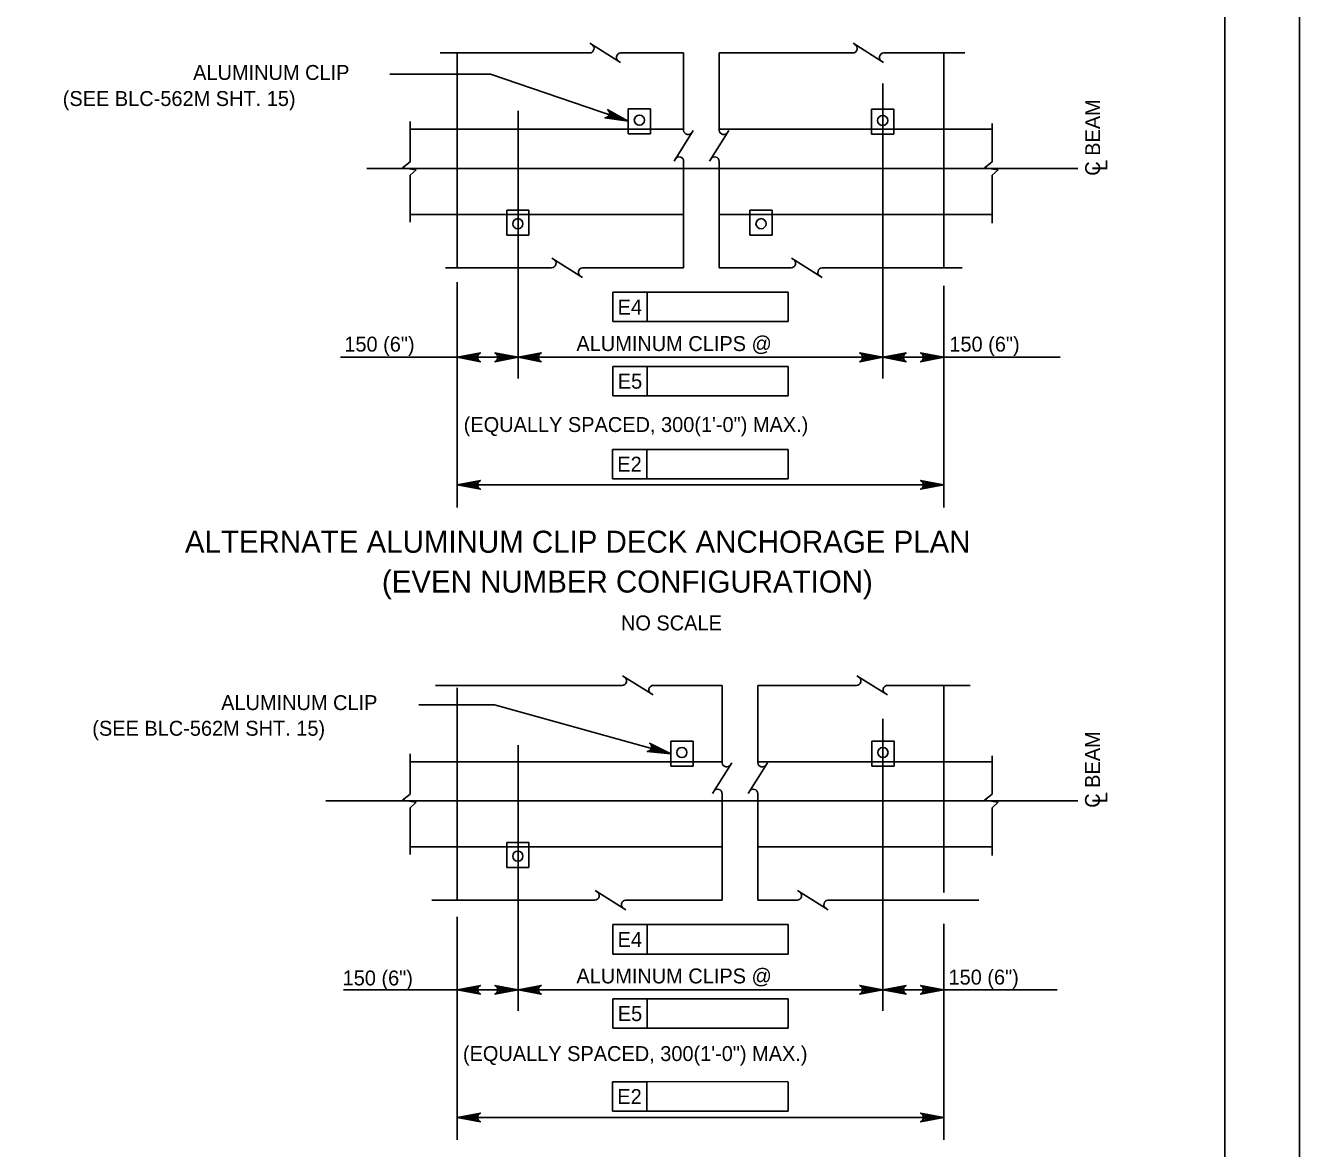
# Model space of a CAD drawing. Extents: x 638263 to 640360, y 293683 to 298655.
# Drawn here: x 639861.3 to 640117.5, y 295708.4 to 295934.1 of the extents above; entities that cross this region are included whole.
import ezdxf

# ---------------------------------------------------------------- set-up
doc = ezdxf.new("R2010")
doc.units = 0
for name, color, linetype in [('2', 7, 'Continuous'), ('3', 7, 'Continuous'), ('4', 7, 'Continuous'), ('8', 7, 'Continuous'), ('9', 7, 'Continuous'), ('PLT-BNDY', 7, 'Continuous')]:
    doc.layers.add(name, color=color, linetype=linetype)

msp = doc.modelspace()

# ---------------------------------------------------------------- linework, layer by layer
at = {"layer": '2'}
for p, q in [((640102.46, 296044.46), (640102.46, 295480.46)), ((639948.08, 295885.4), (639948.08, 295928.58)), ((640045.92, 295885.4), (640045.92, 295928.58)), ((639948.08, 295758.28), (639948.08, 295800.94)), ((640045.92, 295759.8), (640045.92, 295801.5))]:
    msp.add_line(p, q, dxfattribs=at)
at = {"layer": '3'}
for p, q in [((639974.77, 295930.52), (639980.92, 295926.65)), ((640027.67, 295930.52), (640033.82, 295926.65)), ((639944.64, 295928.58), (639974.69, 295928.58)), ((639980.91, 295928.58), (639993.61, 295928.58)), ((639993.61, 295913.01), (639993.61, 295928.58)), ((640000.76, 295913.01), (640000.76, 295928.58)), ((640000.76, 295928.58), (640027.59, 295928.58)), ((640033.81, 295928.58), (640050.15, 295928.58)), ((639938.58, 295906.7), (639938.58, 295914.8)), ((640055.66, 295906.7), (640055.66, 295914.42)), ((639938.58, 295913.23), (639993.61, 295913.23)), ((639991.67, 295906.86), (639995.54, 295913.02)), ((639998.83, 295906.86), (640002.7, 295913.02)), ((640000.76, 295913.23), (640055.66, 295913.23)), ((639937.04, 295905.51), (639938.58, 295906.7)), ((639993.61, 295885.4), (639993.61, 295906.79)), ((640000.76, 295885.4), (640000.76, 295906.79)), ((640054.12, 295905.51), (640055.66, 295906.7)), ((639939.8, 295905.08), (639937.04, 295905.51)), ((639938.58, 295903.99), (639939.8, 295905.08)), ((639938.58, 295894.57), (639938.58, 295903.99)), ((640056.88, 295905.08), (640054.12, 295905.51)), ((640055.66, 295903.99), (640056.88, 295905.08)), ((640055.66, 295894.38), (640055.66, 295903.99)), ((639993.61, 295896.11), (639938.58, 295896.11)), ((640055.66, 295896.11), (640000.76, 295896.11)), ((639945.69, 295885.4), (639967.04, 295885.4)), ((639967.11, 295887.33), (639973.27, 295883.46)), ((639973.26, 295885.4), (639993.61, 295885.4)), ((640000.76, 295885.4), (640015.22, 295885.4)), ((640015.29, 295887.33), (640021.45, 295883.46)), ((640021.44, 295885.4), (640049.62, 295885.4)), ((639981.29, 295803.4), (639987.45, 295799.53)), ((640028.41, 295803.4), (640034.57, 295799.53)), ((639943.68, 295801.46), (639981.22, 295801.46)), ((639987.44, 295801.46), (640001.37, 295801.46)), ((640001.37, 295785.88), (640001.37, 295801.46)), ((640008.53, 295801.46), (640028.34, 295801.46)), ((640008.53, 295785.88), (640008.53, 295801.46)), ((640034.56, 295801.46), (640051.22, 295801.46)), ((639938.58, 295779.58), (639938.58, 295787.68)), ((639938.58, 295786.11), (640001.37, 295786.11)), ((639999.43, 295779.74), (640003.3, 295785.9)), ((640006.59, 295779.74), (640010.46, 295785.9)), ((640008.53, 295786.11), (640055.66, 295786.11)), ((640055.66, 295779.58), (640055.66, 295787.3)), ((639937.04, 295778.39), (639938.58, 295779.58)), ((639939.8, 295777.96), (639937.04, 295778.39)), ((639938.58, 295776.87), (639939.8, 295777.96)), ((640001.37, 295758.28), (640001.37, 295779.67)), ((640008.53, 295758.28), (640008.53, 295779.67)), ((640054.12, 295778.39), (640055.66, 295779.58)), ((640056.88, 295777.96), (640054.12, 295778.39)), ((640055.66, 295776.87), (640056.88, 295777.96)), ((639938.58, 295767.45), (639938.58, 295776.87)), ((640055.66, 295767.26), (640055.66, 295776.87)), ((640001.37, 295768.99), (639938.58, 295768.99)), ((640055.66, 295768.99), (640008.53, 295768.99)), ((639975.79, 295760.21), (639981.95, 295756.34)), ((640016.49, 295760.21), (640022.65, 295756.34)), ((639942.99, 295758.28), (639975.72, 295758.28)), ((639981.94, 295758.28), (640001.37, 295758.28)), ((640008.53, 295758.28), (640016.42, 295758.28)), ((640022.64, 295758.28), (640052.96, 295758.28))]:
    msp.add_line(p, q, dxfattribs=at)
for centre in [(639984.71, 295915.07), (640033.63, 295915.01), (639960.25, 295894.26), (640009.17, 295894.26), (639993.26, 295787.95), (640033.69, 295787.95), (639960.25, 295767.14)]:
    msp.add_circle(centre, 1.02, dxfattribs=at)
for centre, start, end in [((639974.69, 295929.49), 270, 60), ((640027.59, 295929.49), 270, 60), ((639980.99, 295927.68), 95.3286, 237.8672), ((640033.89, 295927.68), 95.3286, 237.8672), ((639994.51, 295913.09), 185.3286, 327.8672), ((640001.67, 295913.09), 185.3286, 327.8672), ((639992.7, 295906.79), 0, 150), ((639999.85, 295906.79), 0, 150), ((639967.04, 295886.31), 270, 60), ((639973.34, 295884.49), 95.3286, 237.8672), ((640015.22, 295886.31), 270, 60), ((640021.52, 295884.49), 95.3286, 237.8672), ((639981.22, 295802.37), 270, 60), ((639987.52, 295800.56), 95.3286, 237.8672), ((640028.34, 295802.37), 270, 60), ((640034.64, 295800.56), 95.3286, 237.8672), ((640002.27, 295785.97), 185.3286, 327.8672), ((640009.43, 295785.97), 185.3286, 327.8672), ((640000.46, 295779.67), 0, 150), ((640007.62, 295779.67), 0, 150), ((639975.72, 295759.19), 270, 60), ((640016.42, 295759.19), 270, 60), ((639982.02, 295757.37), 95.3286, 237.8672), ((640022.72, 295757.37), 95.3286, 237.8672)]:
    msp.add_arc(centre, 0.909, start, end, dxfattribs=at)
at = {"layer": '4'}
for p, q in [((639954.77, 295924.32), (639934.55, 295924.32)), ((640072.85, 295905.34), (639929.93, 295905.34)), ((639979.35, 295880.48), (639979.35, 295874.57)), ((639986.24, 295880.48), (639979.35, 295880.48)), ((639986.24, 295874.57), (639986.24, 295880.48)), ((640014.65, 295880.48), (639986.24, 295880.48)), ((640014.65, 295880.48), (640014.65, 295874.57)), ((639948.08, 295876.08), (639948.08, 295837.24)), ((640045.92, 295876.08), (640045.92, 295837.24)), ((639979.35, 295874.57), (640014.65, 295874.57)), ((639948.08, 295867.4), (639960.31, 295867.4)), ((640033.69, 295867.4), (640045.92, 295867.4)), ((639979.35, 295865.57), (639979.35, 295859.67)), ((639986.24, 295865.57), (639979.35, 295865.57)), ((640014.65, 295865.57), (639986.24, 295865.57)), ((639986.24, 295859.67), (639986.24, 295865.57)), ((640014.65, 295865.57), (640014.65, 295859.67)), ((639979.35, 295859.67), (640014.65, 295859.67)), ((639979.31, 295848.89), (639986.2, 295848.89)), ((639979.31, 295842.99), (639979.31, 295848.89)), ((639986.2, 295842.99), (639986.2, 295848.89)), ((639986.2, 295848.89), (640014.61, 295848.89)), ((640014.61, 295848.89), (640014.61, 295842.99)), ((640045.92, 295841.74), (639948.08, 295841.74)), ((640014.61, 295842.99), (639979.31, 295842.99)), ((639955.6, 295797.56), (639940.34, 295797.56)), ((640072.85, 295778.22), (639921.63, 295778.22)), ((639979.35, 295753.36), (639979.35, 295747.45)), ((639986.24, 295753.36), (639979.35, 295753.36)), ((639986.24, 295747.45), (639986.24, 295753.36)), ((640014.65, 295753.36), (639986.24, 295753.36)), ((640014.65, 295753.36), (640014.65, 295747.45)), ((639948.08, 295748.96), (639948.08, 295710.12)), ((639979.35, 295747.45), (640014.65, 295747.45)), ((640045.92, 295748.96), (640045.92, 295710.12)), ((639948.08, 295740.27), (639960.31, 295740.27)), ((640033.69, 295740.27), (640045.92, 295740.27)), ((639979.35, 295738.45), (639979.35, 295732.55)), ((639986.24, 295738.45), (639979.35, 295738.45)), ((640014.65, 295738.45), (639986.24, 295738.45)), ((639986.24, 295732.55), (639986.24, 295738.45)), ((640014.65, 295738.45), (640014.65, 295732.55)), ((639979.35, 295732.55), (640014.65, 295732.55)), ((639979.31, 295721.77), (639986.13, 295721.78)), ((639979.31, 295715.87), (639979.31, 295721.77)), ((639986.13, 295721.78), (640014.56, 295721.8)), ((639986.2, 295715.87), (639986.2, 295721.77)), ((640014.61, 295721.77), (640014.61, 295715.87)), ((640045.92, 295714.62), (639948.08, 295714.62)), ((640014.61, 295715.87), (639979.31, 295715.87))]:
    msp.add_line(p, q, dxfattribs=at)
for points in [[(639982.48, 295914.85), (639954.77, 295924.32)], [(639982.48, 295914.85), (639977.78, 295915.53), (639978.2, 295915.65), (639978.48, 295915.88), (639978.63, 295916.16), (639978.68, 295916.47), (639978.61, 295916.83), (639978.35, 295917.18), (639982.48, 295914.85), (639978.61, 295916.83), (639978.68, 295916.47), (639982.48, 295914.85), (639978.63, 295916.16), (639978.48, 295915.88), (639982.48, 295914.85), (639978.2, 295915.65)], [(639948.08, 295867.4), (639952.74, 295868.27), (639952.38, 295868.02), (639952.2, 295867.71), (639952.14, 295867.4), (639952.2, 295867.08), (639952.38, 295866.77), (639952.74, 295866.52), (639948.08, 295867.4), (639952.38, 295866.77), (639952.2, 295867.08), (639948.08, 295867.4), (639952.14, 295867.4), (639952.2, 295867.71), (639948.08, 295867.4), (639952.38, 295868.02)], [(639960.31, 295867.4), (639955.65, 295866.52), (639956.01, 295866.77), (639956.19, 295867.08), (639956.25, 295867.4), (639956.19, 295867.71), (639956.01, 295868.02), (639955.65, 295868.27), (639960.31, 295867.4), (639956.01, 295868.02), (639956.19, 295867.71), (639960.31, 295867.4), (639956.25, 295867.4), (639956.19, 295867.08), (639960.31, 295867.4), (639956.01, 295866.77)], [(639960.31, 295867.4), (639964.97, 295868.27), (639964.61, 295868.02), (639964.43, 295867.71), (639964.37, 295867.4), (639964.43, 295867.08), (639964.61, 295866.77), (639964.97, 295866.52), (639960.31, 295867.4), (639964.61, 295866.77), (639964.43, 295867.08), (639960.31, 295867.4), (639964.37, 295867.4), (639964.43, 295867.71), (639960.31, 295867.4), (639964.61, 295868.02)], [(640033.69, 295867.4), (640029.03, 295866.52), (640029.39, 295866.77), (640029.57, 295867.08), (640029.63, 295867.4), (640029.57, 295867.71), (640029.39, 295868.02), (640029.03, 295868.27), (640033.69, 295867.4), (640029.39, 295868.02), (640029.57, 295867.71), (640033.69, 295867.4), (640029.63, 295867.4), (640029.57, 295867.08), (640033.69, 295867.4), (640029.39, 295866.77)], [(640033.69, 295867.4), (640038.35, 295868.27), (640037.99, 295868.02), (640037.81, 295867.71), (640037.75, 295867.4), (640037.81, 295867.08), (640037.99, 295866.77), (640038.35, 295866.52), (640033.69, 295867.4), (640037.99, 295866.77), (640037.81, 295867.08), (640033.69, 295867.4), (640037.75, 295867.4), (640037.81, 295867.71), (640033.69, 295867.4), (640037.99, 295868.02)], [(640045.92, 295867.4), (640041.26, 295866.52), (640041.62, 295866.77), (640041.8, 295867.08), (640041.86, 295867.4), (640041.8, 295867.71), (640041.62, 295868.02), (640041.26, 295868.27), (640045.92, 295867.4), (640041.62, 295868.02), (640041.8, 295867.71), (640045.92, 295867.4), (640041.86, 295867.4), (640041.8, 295867.08), (640045.92, 295867.4), (640041.62, 295866.77)], [(639948.08, 295841.74), (639952.74, 295842.61), (639952.38, 295842.36), (639952.2, 295842.05), (639952.14, 295841.74), (639952.2, 295841.43), (639952.38, 295841.11), (639952.74, 295840.87), (639948.08, 295841.74), (639952.38, 295841.11), (639952.2, 295841.43), (639948.08, 295841.74), (639952.14, 295841.74), (639952.2, 295842.05), (639948.08, 295841.74), (639952.38, 295842.36)], [(640045.92, 295841.74), (640041.26, 295840.87), (640041.62, 295841.11), (640041.8, 295841.43), (640041.86, 295841.74), (640041.8, 295842.05), (640041.62, 295842.36), (640041.26, 295842.61), (640045.92, 295841.74), (640041.62, 295842.36), (640041.8, 295842.05), (640045.92, 295841.74), (640041.86, 295841.74), (640041.8, 295841.43), (640045.92, 295841.74), (640041.62, 295841.11)], [(639991.03, 295787.72), (639955.6, 295797.56)], [(639991.03, 295787.72), (639986.3, 295788.13), (639986.72, 295788.27), (639986.98, 295788.52), (639987.12, 295788.81), (639987.15, 295789.13), (639987.05, 295789.48), (639986.77, 295789.81), (639991.03, 295787.72), (639987.05, 295789.48), (639987.15, 295789.13), (639991.03, 295787.72), (639987.12, 295788.81), (639986.98, 295788.52), (639991.03, 295787.72), (639986.72, 295788.27)], [(639948.08, 295740.27), (639952.74, 295741.15), (639952.38, 295740.9), (639952.2, 295740.59), (639952.14, 295740.27), (639952.2, 295739.96), (639952.38, 295739.65), (639952.74, 295739.4), (639948.08, 295740.27), (639952.38, 295739.65), (639952.2, 295739.96), (639948.08, 295740.27), (639952.14, 295740.27), (639952.2, 295740.59), (639948.08, 295740.27), (639952.38, 295740.9)], [(639960.31, 295740.27), (639955.65, 295739.4), (639956.01, 295739.65), (639956.19, 295739.96), (639956.25, 295740.27), (639956.19, 295740.59), (639956.01, 295740.9), (639955.65, 295741.15), (639960.31, 295740.27), (639956.01, 295740.9), (639956.19, 295740.59), (639960.31, 295740.27), (639956.25, 295740.27), (639956.19, 295739.96), (639960.31, 295740.27), (639956.01, 295739.65)], [(639960.31, 295740.27), (639964.97, 295741.15), (639964.61, 295740.9), (639964.43, 295740.59), (639964.37, 295740.27), (639964.43, 295739.96), (639964.61, 295739.65), (639964.97, 295739.4), (639960.31, 295740.27), (639964.61, 295739.65), (639964.43, 295739.96), (639960.31, 295740.27), (639964.37, 295740.27), (639964.43, 295740.59), (639960.31, 295740.27), (639964.61, 295740.9)], [(640033.69, 295740.27), (640029.03, 295739.4), (640029.39, 295739.65), (640029.57, 295739.96), (640029.63, 295740.27), (640029.57, 295740.59), (640029.39, 295740.9), (640029.03, 295741.15), (640033.69, 295740.27), (640029.39, 295740.9), (640029.57, 295740.59), (640033.69, 295740.27), (640029.63, 295740.27), (640029.57, 295739.96), (640033.69, 295740.27), (640029.39, 295739.65)], [(640033.69, 295740.27), (640038.35, 295741.15), (640037.99, 295740.9), (640037.81, 295740.59), (640037.75, 295740.27), (640037.81, 295739.96), (640037.99, 295739.65), (640038.35, 295739.4), (640033.69, 295740.27), (640037.99, 295739.65), (640037.81, 295739.96), (640033.69, 295740.27), (640037.75, 295740.27), (640037.81, 295740.59), (640033.69, 295740.27), (640037.99, 295740.9)], [(640045.92, 295740.27), (640041.26, 295739.4), (640041.62, 295739.65), (640041.8, 295739.96), (640041.86, 295740.27), (640041.8, 295740.59), (640041.62, 295740.9), (640041.26, 295741.15), (640045.92, 295740.27), (640041.62, 295740.9), (640041.8, 295740.59), (640045.92, 295740.27), (640041.86, 295740.27), (640041.8, 295739.96), (640045.92, 295740.27), (640041.62, 295739.65)], [(639948.08, 295714.62), (639952.74, 295715.49), (639952.38, 295715.24), (639952.2, 295714.93), (639952.14, 295714.62), (639952.2, 295714.31), (639952.38, 295713.99), (639952.74, 295713.74), (639948.08, 295714.62), (639952.38, 295713.99), (639952.2, 295714.31), (639948.08, 295714.62), (639952.14, 295714.62), (639952.2, 295714.93), (639948.08, 295714.62), (639952.38, 295715.24)], [(640045.92, 295714.62), (640041.26, 295713.74), (640041.62, 295713.99), (640041.8, 295714.31), (640041.86, 295714.62), (640041.8, 295714.93), (640041.62, 295715.24), (640041.26, 295715.49), (640045.92, 295714.62), (640041.62, 295715.24), (640041.8, 295714.93), (640045.92, 295714.62), (640041.86, 295714.62), (640041.8, 295714.31), (640045.92, 295714.62), (640041.62, 295713.99)]]:
    msp.add_lwpolyline(points, dxfattribs=at)
for points in [[(639982.48, 295914.85), (639982.37, 295914.91), (639982.35, 295914.86)], [(639991.03, 295787.72), (639990.92, 295787.78), (639990.91, 295787.73)]]:
    msp.add_lwpolyline(points, close=True, dxfattribs=at)
at = {"layer": '8'}
for p, q in [((640033.69, 295922.45), (640033.69, 295863.14)), ((639960.31, 295916.98), (639960.31, 295863.14)), ((640033.63, 295915.01), (640033.63, 295915.01)), ((640050.48, 295913.23), (640050.48, 295913.23)), ((639942.75, 295896.11), (639942.75, 295896.11)), ((640041.02, 295896.11), (640041.02, 295896.11)), ((639960.25, 295894.26), (639960.25, 295894.26)), ((639948.08, 295882.48), (639948.08, 295863.14)), ((640045.92, 295881.78), (640045.92, 295863.14)), ((639924.6, 295867.4), (639948.08, 295867.4)), ((639960.31, 295867.4), (640033.69, 295867.4)), ((640045.92, 295867.4), (640069.33, 295867.4)), ((640033.69, 295794.75), (640033.69, 295736.02)), ((639960.31, 295789.43), (639960.31, 295736.02)), ((640050.48, 295786.11), (640050.48, 295786.11)), ((639942.75, 295768.99), (639942.75, 295768.99)), ((640041.02, 295768.99), (640041.02, 295768.99)), ((639960.25, 295767.14), (639960.25, 295767.14)), ((639948.08, 295754.94), (639948.08, 295736.02)), ((640045.92, 295753.55), (640045.92, 295736.02)), ((639925.23, 295740.27), (639948.08, 295740.27)), ((639960.31, 295740.27), (640033.69, 295740.27)), ((640045.92, 295740.27), (640068.7, 295740.27))]:
    msp.add_line(p, q, dxfattribs=at)
at = {"layer": '9'}
for p, q in [((639982.48, 295917.35), (639986.94, 295917.35)), ((639982.48, 295912.34), (639982.48, 295917.35)), ((639986.94, 295917.35), (639986.94, 295912.34)), ((640031.39, 295917.29), (640035.86, 295917.29)), ((640031.39, 295912.29), (640031.39, 295917.29)), ((640035.86, 295917.29), (640035.86, 295912.29)), ((639986.94, 295912.34), (639982.48, 295912.34)), ((640035.86, 295912.29), (640031.39, 295912.29)), ((639958.02, 295896.99), (639958.02, 295891.98)), ((639962.49, 295896.99), (639958.02, 295896.99)), ((639962.49, 295891.98), (639962.49, 295896.99)), ((640006.93, 295896.99), (640006.93, 295891.98)), ((640011.4, 295896.99), (640006.93, 295896.99)), ((640011.4, 295891.98), (640011.4, 295896.99)), ((639958.02, 295891.98), (639962.49, 295891.98)), ((640006.93, 295891.98), (640011.4, 295891.98)), ((639991.03, 295790.22), (639995.5, 295790.22)), ((639991.03, 295785.22), (639991.03, 295790.22)), ((639995.5, 295790.22), (639995.5, 295785.22)), ((640031.45, 295785.22), (640031.45, 295790.22)), ((640031.45, 295790.22), (640035.92, 295790.22)), ((640035.92, 295790.22), (640035.92, 295785.22)), ((639995.5, 295785.22), (639991.03, 295785.22)), ((640035.92, 295785.22), (640031.45, 295785.22)), ((639958.02, 295769.87), (639958.02, 295764.86)), ((639962.49, 295769.87), (639958.02, 295769.87)), ((639962.49, 295764.86), (639962.49, 295769.87)), ((639958.02, 295764.86), (639962.49, 295764.86))]:
    msp.add_line(p, q, dxfattribs=at)
at = {"layer": 'PLT-BNDY'}
msp.add_lwpolyline([(639276.46, 296059.46), (640117.46, 296059.46), (640117.46, 295465.46), (639276.46, 295465.46)], close=True, dxfattribs=at)

# ---------------------------------------------------------------- texts
at = {"layer": '4'}
for s, height, p in [('ALUMINUM CLIP', 3, (639894.97, 295923.16)), ('(SEE BLC-562M SHT. 15)', 3, (639868.75, 295917.92)), ('E4', 3, (639980.33, 295876)), ('150 (6")', 3, (639925.37, 295868.55)), ('ALUMINUM CLIPS @', 3, (639972.04, 295868.66)), ('150 (6")', 3, (640047.04, 295868.55)), ('E5', 3, (639980.36, 295861.1)), ('(EQUALLY SPACED, 300(1\'-0") MAX.)', 3, (639949.38, 295852.39)), ('E2', 3, (639980.27, 295844.42)), ('ALTERNATE ALUMINUM CLIP DECK ANCHORAGE PLAN', 4.4292, (639893.32, 295828.12)), ('(EVEN NUMBER CONFIGURATION)', 4.4292, (639932.93, 295820.11)), ('NO SCALE', 3, (639981, 295812.51)), ('ALUMINUM CLIP', 3, (639900.6, 295796.49)), ('(SEE BLC-562M SHT. 15)', 3, (639874.69, 295791.33)), ('E4', 3, (639980.33, 295748.88)), ('150 (6")', 3, (639925.03, 295741.14)), ('ALUMINUM CLIPS @', 3, (639972.04, 295741.54)), ('150 (6")', 3, (640046.87, 295741.31)), ('E5', 3, (639980.36, 295733.98)), ('(EQUALLY SPACED, 300(1\'-0") MAX.)', 3, (639949.22, 295725.94)), ('E2', 3, (639980.27, 295717.3))]:
    msp.add_text(s, height=height, dxfattribs=at).set_placement(p)
for s, p in [('C BEAM', (640077.36, 295903.9)), ('L', (640078.82, 295904.88)), ('C BEAM', (640077.32, 295776.85)), ('L', (640078.82, 295777.76))]:
    msp.add_text(s, height=3, rotation=90, dxfattribs=at).set_placement(p)

doc.saveas('drawing.dxf')
